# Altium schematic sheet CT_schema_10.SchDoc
size 274 x 160 mm
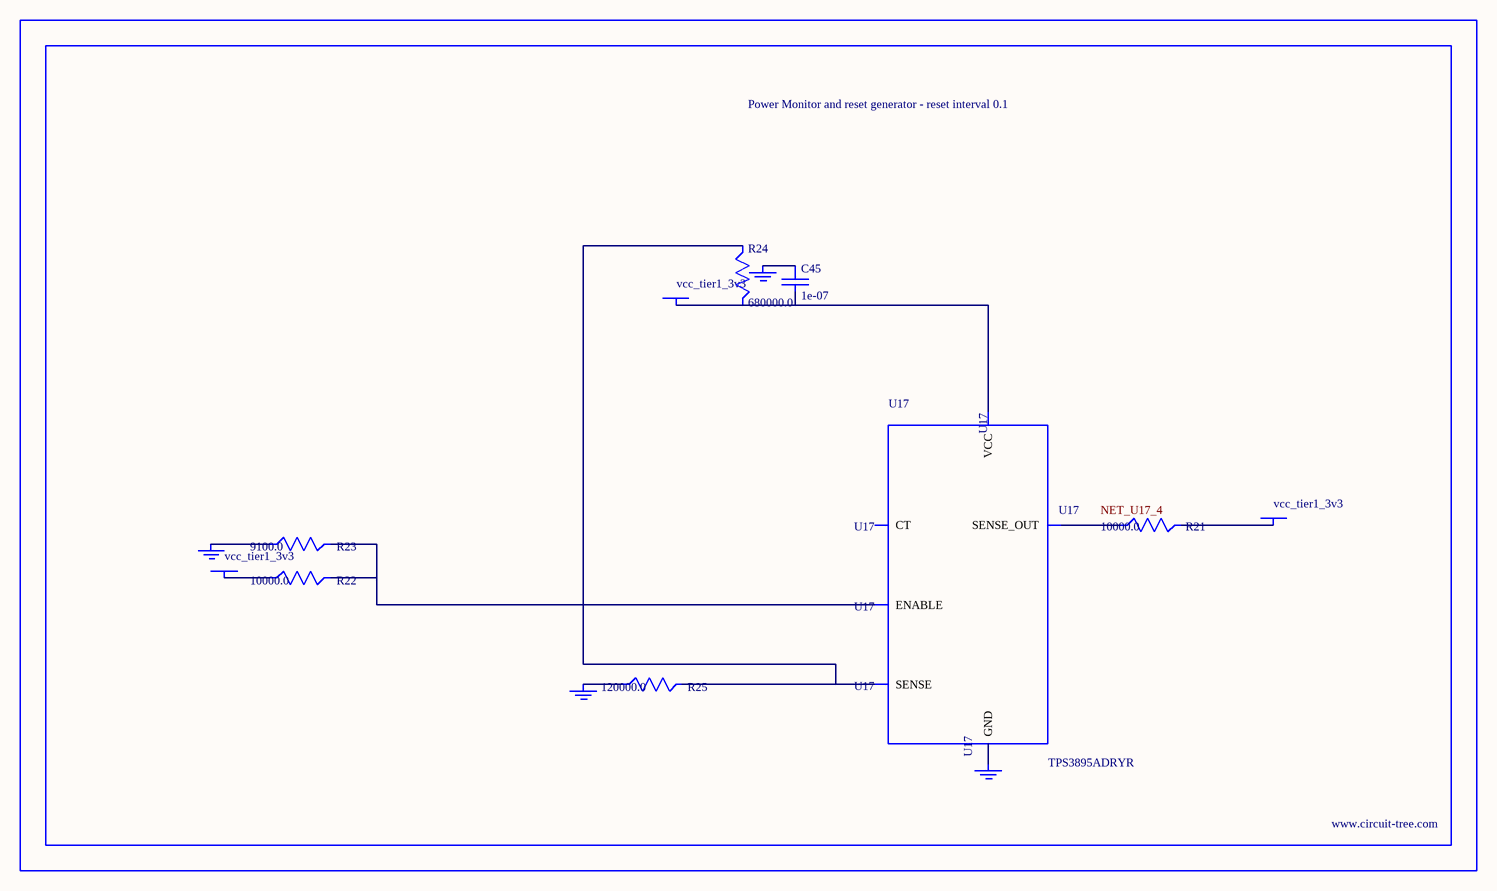
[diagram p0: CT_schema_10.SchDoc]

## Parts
BORDER9  (no value)
C45  1e-07  [C0402]
GND_INSTANCE_9_0  (no value)
GND_INSTANCE_9_1  (no value)
GND_INSTANCE_9_2  (no value)
GND_INSTANCE_9_3  (no value)
POWER_INSTANCE_9_0  vcc_tier1_3v3
POWER_INSTANCE_9_1  vcc_tier1_3v3
POWER_INSTANCE_9_2  vcc_tier1_3v3
R21  10000.0  [R0603]
R22  10000.0  [R0603]
R23  9100.0  [R0603]
R24  680000.0  [R0603]
R25  120000.0  [R0603]
U17  TPS3895ADRYR  [SON-6]

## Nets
NetC45_1: C45.1 GND_INSTANCE_9_2.0(GND)
NetC45_2: C45.2 POWER_INSTANCE_9_2.0(PWR) R24.2 U17.6(VCC)
NetGND_INSTANCE_9_0_0: GND_INSTANCE_9_0.0(GND) R23.1
NetGND_INSTANCE_9_1_0: GND_INSTANCE_9_1.0(GND) R25.1
NetGND_INSTANCE_9_3_0: GND_INSTANCE_9_3.0(GND) U17.2(GND)
NetPOWER_INSTANCE_9_0_0: POWER_INSTANCE_9_0.0(PWR) R22.1
NetPOWER_INSTANCE_9_1_0: POWER_INSTANCE_9_1.0(PWR) R21.2
NetR21_1: R21.1 U17.4(SENSE_OUT)
NetR22_2: R22.2 R23.2 U17.1(ENABLE)
NetR24_1: R24.1 R25.2 U17.3(SENSE)

Not connected (* = marked no-connect by the designer): U17 5(CT)

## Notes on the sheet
- Labels drawn without touching a wire or pin: NET_U17_4

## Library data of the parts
BORDER9 = BORDER_PAGE9
C45 = C0402C104K3RACTU
GND_INSTANCE_9_0-GND_INSTANCE_9_3 = GND
POWER_INSTANCE_9_0-POWER_INSTANCE_9_2 = PWR
R21 R22 = RC0603JR-0710KL
R23 = RC0603JR-079K1L
R24 = RC0603JR-07680KL
R25 = RC0603JR-07120KL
